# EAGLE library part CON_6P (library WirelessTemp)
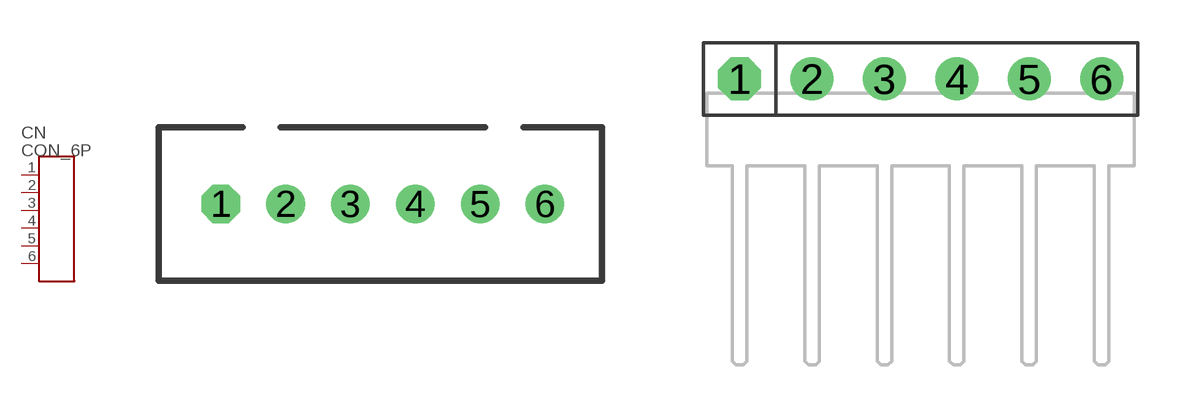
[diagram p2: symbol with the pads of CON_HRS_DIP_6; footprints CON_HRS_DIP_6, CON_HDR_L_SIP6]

Designator prefix CN

## CON_6P  [CON_HRS_DIP_6]
1  1  pas
2  2  pas
3  3  pas
4  4  pas
5  5  pas
6  6  pas

## CON_6PHDR_L  [CON_HDR_L_SIP6]
Pads as for CON_HRS_DIP_6

## CON_6P2X3  [CON_HDR_2X3]
Pads as for CON_HRS_DIP_6

## Footprint CON_HRS_DIP_6 (pad centres in mm)
drill 1 octagon: 1 -6.35,0
drill 1 round: 2 -3.81,0; 3 -1.27,0; 4 1.27,0; 5 3.81,0; 6 6.35,0

## Footprint CON_HDR_L_SIP6 (pad centres in mm)
drill 1 octagon: 1 -6.35,0
drill 1 round: 2 -3.81,0; 3 -1.27,0; 4 1.27,0; 5 3.81,0; 6 6.35,0

## Footprint CON_HDR_2X3 (pad centres in mm)
drill 1 round: 1 -2.54,1.27; 2 0,1.27; 3 2.54,1.27; 4 -2.54,-1.27; 5 0,-1.27; 6 2.54,-1.27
